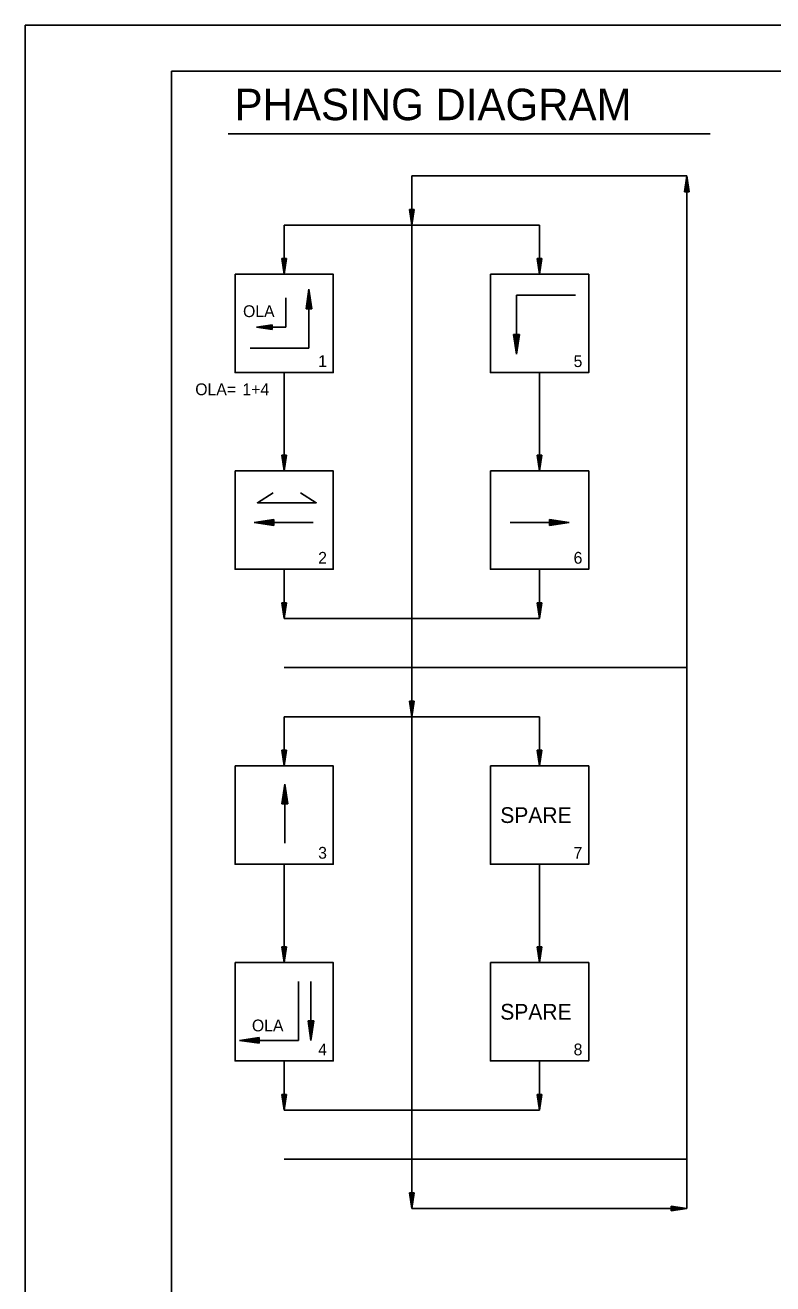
# Model space of a CAD drawing. Extents: x 1710114 to 1711114, y 557211 to 557851.
# Drawn here: x 1710114.3 to 1710304.6, y 557531.1 to 557851.1 of the extents above; entities that cross this region are included whole.
import ezdxf

# ---------------------------------------------------------------- set-up
doc = ezdxf.new("R2010")
doc.units = 0
for name, color, linetype in [('E_Existing ROW', 7, 'Continuous'), ('R_Alt Surface', 7, 'Continuous'), ('R_Alt Surface Annot', 7, 'Continuous'), ('R_Detour', 7, 'Continuous'), ('R_Dimension', 7, 'Continuous')]:
    doc.layers.add(name, color=color, linetype=linetype)

msp = doc.modelspace()

# ---------------------------------------------------------------- linework, layer by layer
at = {"layer": 'E_Existing ROW'}
for p, q in [((1710212.73, 557550.31), (1710212.73, 557812.81)), ((1710212.73, 557812.81), (1710282.73, 557812.81)), ((1710282.73, 557812.81), (1710282.73, 557550.31)), ((1710180.23, 557787.81), (1710180.23, 557800.31)), ((1710180.23, 557800.31), (1710245.23, 557800.31)), ((1710245.23, 557787.81), (1710245.23, 557800.31)), ((1710185.8, 557779.07), (1710186.55, 557784.07)), ((1710186.55, 557769.07), (1710186.55, 557784.07)), ((1710186.55, 557784.07), (1710187.3, 557779.07)), ((1710180.67, 557781.85), (1710180.67, 557774.35)), ((1710186.55, 557783.24), (1710185.92, 557779.07)), ((1710186.05, 557779.07), (1710186.55, 557782.38)), ((1710186.55, 557781.54), (1710186.18, 557779.07)), ((1710187.17, 557779.07), (1710186.55, 557783.24)), ((1710186.55, 557782.38), (1710187.05, 557779.07)), ((1710186.92, 557779.07), (1710186.55, 557781.54)), ((1710254.34, 557782.53), (1710239.34, 557782.53)), ((1710239.34, 557782.53), (1710239.34, 557767.53)), ((1710185.8, 557779.07), (1710187.3, 557779.07)), ((1710186.31, 557779.07), (1710186.55, 557780.7)), ((1710186.55, 557779.86), (1710186.43, 557779.07)), ((1710186.55, 557780.7), (1710186.79, 557779.07)), ((1710186.67, 557779.07), (1710186.55, 557779.86)), ((1710177.17, 557774.95), (1710173.17, 557774.35)), ((1710173.84, 557774.35), (1710177.17, 557774.85)), ((1710177.17, 557774.75), (1710174.53, 557774.35)), ((1710175.2, 557774.35), (1710177.17, 557774.65)), ((1710177.17, 557774.54), (1710175.87, 557774.35)), ((1710176.54, 557774.35), (1710177.17, 557774.44)), ((1710177.17, 557774.95), (1710177.17, 557773.75)), ((1710180.67, 557774.35), (1710173.17, 557774.35)), ((1710173.17, 557774.35), (1710177.17, 557773.75)), ((1710177.17, 557773.85), (1710173.84, 557774.35)), ((1710174.53, 557774.35), (1710177.17, 557773.95)), ((1710177.17, 557774.05), (1710175.2, 557774.35)), ((1710175.87, 557774.35), (1710177.17, 557774.15)), ((1710177.17, 557774.25), (1710176.54, 557774.35)), ((1710239.34, 557767.53), (1710238.59, 557772.53)), ((1710240.09, 557772.53), (1710238.59, 557772.53)), ((1710238.71, 557772.53), (1710239.34, 557768.37)), ((1710239.34, 557769.23), (1710238.84, 557772.53)), ((1710238.96, 557772.53), (1710239.34, 557770.06)), ((1710239.34, 557770.91), (1710239.09, 557772.53)), ((1710239.22, 557772.53), (1710239.34, 557771.74)), ((1710239.34, 557771.74), (1710239.45, 557772.53)), ((1710239.58, 557772.53), (1710239.34, 557770.91)), ((1710239.34, 557770.06), (1710239.71, 557772.53)), ((1710239.83, 557772.53), (1710239.34, 557769.23)), ((1710239.34, 557768.37), (1710239.96, 557772.53)), ((1710240.09, 557772.53), (1710239.34, 557767.53)), ((1710171.55, 557769.07), (1710186.55, 557769.07)), ((1710180.23, 557737.81), (1710180.23, 557762.81)), ((1710245.23, 557737.81), (1710245.23, 557762.81)), ((1710172.6, 557724.72), (1710177.6, 557725.47)), ((1710187.6, 557724.72), (1710172.6, 557724.72)), ((1710177.6, 557723.97), (1710172.6, 557724.72)), ((1710177.6, 557725.34), (1710173.43, 557724.72)), ((1710173.43, 557724.72), (1710177.6, 557724.09)), ((1710174.29, 557724.72), (1710177.6, 557725.21)), ((1710177.6, 557724.22), (1710174.29, 557724.72)), ((1710177.6, 557725.09), (1710175.13, 557724.72)), ((1710175.13, 557724.72), (1710177.6, 557724.34)), ((1710175.97, 557724.72), (1710177.6, 557724.96)), ((1710177.6, 557724.47), (1710175.97, 557724.72)), ((1710177.6, 557724.83), (1710176.81, 557724.72)), ((1710176.81, 557724.72), (1710177.6, 557724.6)), ((1710177.6, 557723.97), (1710177.6, 557725.47)), ((1710237.76, 557724.72), (1710252.76, 557724.72)), ((1710247.76, 557725.47), (1710252.76, 557724.72)), ((1710247.76, 557725.47), (1710247.76, 557723.97)), ((1710251.92, 557724.72), (1710247.76, 557725.34)), ((1710247.76, 557725.21), (1710251.06, 557724.72)), ((1710250.23, 557724.72), (1710247.76, 557725.09)), ((1710247.76, 557724.96), (1710249.38, 557724.72)), ((1710248.55, 557724.72), (1710247.76, 557724.83)), ((1710252.76, 557724.72), (1710247.76, 557723.97)), ((1710247.76, 557724.09), (1710251.92, 557724.72)), ((1710251.06, 557724.72), (1710247.76, 557724.22)), ((1710247.76, 557724.34), (1710250.23, 557724.72)), ((1710249.38, 557724.72), (1710247.76, 557724.47)), ((1710247.76, 557724.6), (1710248.55, 557724.72)), ((1710180.23, 557700.31), (1710180.23, 557712.81)), ((1710245.23, 557700.31), (1710245.23, 557712.81)), ((1710180.23, 557700.31), (1710245.23, 557700.31)), ((1710180.23, 557687.81), (1710282.73, 557687.81)), ((1710180.23, 557675.31), (1710245.23, 557675.31)), ((1710180.23, 557662.81), (1710180.23, 557675.31)), ((1710245.23, 557662.81), (1710245.23, 557675.31)), ((1710179.66, 557653.15), (1710180.41, 557658.15)), ((1710180.41, 557657.32), (1710179.79, 557653.15)), ((1710179.92, 557653.15), (1710180.41, 557656.46)), ((1710180.41, 557643.15), (1710180.41, 557658.15)), ((1710180.41, 557658.15), (1710181.16, 557653.15)), ((1710181.04, 557653.15), (1710180.41, 557657.32)), ((1710180.41, 557656.46), (1710180.91, 557653.15)), ((1710179.66, 557653.15), (1710181.16, 557653.15)), ((1710180.41, 557655.63), (1710180.04, 557653.15)), ((1710180.17, 557653.15), (1710180.41, 557654.78)), ((1710180.41, 557653.94), (1710180.3, 557653.15)), ((1710180.79, 557653.15), (1710180.41, 557655.63)), ((1710180.41, 557654.78), (1710180.66, 557653.15)), ((1710180.53, 557653.15), (1710180.41, 557653.94)), ((1710180.23, 557612.81), (1710180.23, 557637.81)), ((1710245.23, 557612.81), (1710245.23, 557637.81)), ((1710183.86, 557608.04), (1710183.86, 557593.04)), ((1710187.06, 557608.04), (1710187.06, 557593.04)), ((1710187.06, 557593.04), (1710186.31, 557598.04)), ((1710187.81, 557598.04), (1710186.31, 557598.04)), ((1710186.43, 557598.04), (1710187.06, 557593.87)), ((1710187.06, 557594.73), (1710186.56, 557598.04)), ((1710186.69, 557598.04), (1710187.06, 557595.57)), ((1710187.06, 557596.41), (1710186.81, 557598.04)), ((1710186.94, 557598.04), (1710187.06, 557597.25)), ((1710187.06, 557597.25), (1710187.18, 557598.04)), ((1710187.3, 557598.04), (1710187.06, 557596.41)), ((1710187.06, 557595.57), (1710187.43, 557598.04)), ((1710187.56, 557598.04), (1710187.06, 557594.73)), ((1710187.06, 557593.87), (1710187.68, 557598.04)), ((1710187.81, 557598.04), (1710187.06, 557593.04)), ((1710173.86, 557593.79), (1710168.86, 557593.04)), ((1710183.86, 557593.04), (1710168.86, 557593.04)), ((1710168.86, 557593.04), (1710173.86, 557592.29)), ((1710169.69, 557593.04), (1710173.86, 557593.66)), ((1710173.86, 557592.41), (1710169.69, 557593.04)), ((1710173.86, 557593.54), (1710170.55, 557593.04)), ((1710170.55, 557593.04), (1710173.86, 557592.54)), ((1710171.38, 557593.04), (1710173.86, 557593.41)), ((1710173.86, 557592.67), (1710171.38, 557593.04)), ((1710173.86, 557593.28), (1710172.23, 557593.04)), ((1710172.23, 557593.04), (1710173.86, 557592.79)), ((1710173.07, 557593.04), (1710173.86, 557593.16)), ((1710173.86, 557592.92), (1710173.07, 557593.04)), ((1710173.86, 557593.79), (1710173.86, 557592.29)), ((1710180.23, 557575.31), (1710180.23, 557587.81)), ((1710245.23, 557575.31), (1710245.23, 557587.81)), ((1710180.23, 557575.31), (1710245.23, 557575.31)), ((1710180.23, 557562.81), (1710282.73, 557562.81)), ((1710212.73, 557550.31), (1710282.73, 557550.31))]:
    msp.add_line(p, q, dxfattribs=at)
for points in [[(1710167.73, 557787.81), (1710192.73, 557787.81), (1710192.73, 557762.81), (1710167.73, 557762.81)], [(1710232.73, 557787.81), (1710257.73, 557787.81), (1710257.73, 557762.81), (1710232.73, 557762.81)], [(1710167.73, 557737.81), (1710192.73, 557737.81), (1710192.73, 557712.81), (1710167.73, 557712.81)], [(1710232.73, 557737.81), (1710257.73, 557737.81), (1710257.73, 557712.81), (1710232.73, 557712.81)], [(1710167.73, 557662.81), (1710192.73, 557662.81), (1710192.73, 557637.81), (1710167.73, 557637.81)], [(1710232.73, 557662.81), (1710257.73, 557662.81), (1710257.73, 557637.81), (1710232.73, 557637.81)], [(1710167.73, 557612.81), (1710192.73, 557612.81), (1710192.73, 557587.81), (1710167.73, 557587.81)], [(1710232.73, 557612.81), (1710257.73, 557612.81), (1710257.73, 557587.81), (1710232.73, 557587.81)]]:
    msp.add_lwpolyline(points, close=True, dxfattribs=at)
msp.add_lwpolyline([(1710177.41, 557732.22), (1710173.41, 557729.72), (1710188.41, 557729.72), (1710184.41, 557732.22)], dxfattribs=at)
at = {"layer": 'R_Alt Surface'}
for p, q in [((1710151.54, 557839.47), (1711100.08, 557839.47)), ((1710151.54, 557223.09), (1710151.54, 557839.47))]:
    msp.add_line(p, q, dxfattribs=at)
at = {"layer": 'R_Alt Surface Annot'}
msp.add_line((1710114.34, 557851.15), (1711114.34, 557851.15), dxfattribs=at)
msp.add_lwpolyline([(1710114.32, 557851.15), (1711114.34, 557851.15), (1711114.34, 557211.14), (1710114.32, 557211.14)], close=True, dxfattribs=at)
at = {"layer": 'R_Detour'}
for p, q in [((1710282.13, 557808.81), (1710282.73, 557812.81)), ((1710283.33, 557808.81), (1710282.73, 557812.81)), ((1710282.23, 557808.81), (1710282.73, 557812.14)), ((1710282.34, 557808.81), (1710282.73, 557811.45)), ((1710282.44, 557808.81), (1710282.73, 557810.79)), ((1710282.54, 557808.81), (1710282.73, 557810.11)), ((1710283.23, 557808.81), (1710282.73, 557812.14)), ((1710283.13, 557808.81), (1710282.73, 557811.45)), ((1710283.03, 557808.81), (1710282.73, 557810.79)), ((1710282.93, 557808.81), (1710282.73, 557810.11)), ((1710282.13, 557808.81), (1710283.33, 557808.81)), ((1710282.64, 557808.81), (1710282.73, 557809.44)), ((1710282.83, 557808.81), (1710282.73, 557809.44)), ((1710212.13, 557804.31), (1710212.73, 557800.31)), ((1710213.33, 557804.31), (1710212.13, 557804.31)), ((1710212.23, 557804.31), (1710212.73, 557800.98)), ((1710212.34, 557804.31), (1710212.73, 557801.67)), ((1710212.44, 557804.31), (1710212.73, 557802.33)), ((1710212.54, 557804.31), (1710212.73, 557803.01)), ((1710212.64, 557804.31), (1710212.73, 557803.68)), ((1710213.33, 557804.31), (1710212.73, 557800.31)), ((1710212.93, 557804.31), (1710212.73, 557803.01)), ((1710213.13, 557804.31), (1710212.73, 557801.67)), ((1710213.23, 557804.31), (1710212.73, 557800.98)), ((1710213.03, 557804.31), (1710212.73, 557802.33)), ((1710212.83, 557804.31), (1710212.73, 557803.68)), ((1710179.63, 557791.81), (1710180.23, 557787.81)), ((1710180.83, 557791.81), (1710179.63, 557791.81)), ((1710179.73, 557791.81), (1710180.23, 557788.48)), ((1710179.84, 557791.81), (1710180.23, 557789.17)), ((1710179.94, 557791.81), (1710180.23, 557789.83)), ((1710180.04, 557791.81), (1710180.23, 557790.51)), ((1710180.14, 557791.81), (1710180.23, 557791.18)), ((1710180.83, 557791.81), (1710180.23, 557787.81)), ((1710180.43, 557791.81), (1710180.23, 557790.51)), ((1710180.63, 557791.81), (1710180.23, 557789.17)), ((1710180.73, 557791.81), (1710180.23, 557788.48)), ((1710180.53, 557791.81), (1710180.23, 557789.83)), ((1710180.33, 557791.81), (1710180.23, 557791.18)), ((1710244.63, 557791.81), (1710245.23, 557787.81)), ((1710245.83, 557791.81), (1710244.63, 557791.81)), ((1710244.73, 557791.81), (1710245.23, 557788.48)), ((1710244.84, 557791.81), (1710245.23, 557789.17)), ((1710244.94, 557791.81), (1710245.23, 557789.83)), ((1710245.04, 557791.81), (1710245.23, 557790.51)), ((1710245.14, 557791.81), (1710245.23, 557791.18)), ((1710245.83, 557791.81), (1710245.23, 557787.81)), ((1710245.43, 557791.81), (1710245.23, 557790.51)), ((1710245.63, 557791.81), (1710245.23, 557789.17)), ((1710245.73, 557791.81), (1710245.23, 557788.48)), ((1710245.53, 557791.81), (1710245.23, 557789.83)), ((1710245.33, 557791.81), (1710245.23, 557791.18)), ((1710179.63, 557741.81), (1710180.23, 557737.81)), ((1710180.83, 557741.81), (1710179.63, 557741.81)), ((1710179.73, 557741.81), (1710180.23, 557738.48)), ((1710179.84, 557741.81), (1710180.23, 557739.17)), ((1710179.94, 557741.81), (1710180.23, 557739.83)), ((1710180.04, 557741.81), (1710180.23, 557740.51)), ((1710180.14, 557741.81), (1710180.23, 557741.18)), ((1710180.83, 557741.81), (1710180.23, 557737.81)), ((1710180.43, 557741.81), (1710180.23, 557740.51)), ((1710180.63, 557741.81), (1710180.23, 557739.17)), ((1710180.73, 557741.81), (1710180.23, 557738.48)), ((1710180.53, 557741.81), (1710180.23, 557739.83)), ((1710180.33, 557741.81), (1710180.23, 557741.18)), ((1710244.63, 557741.81), (1710245.23, 557737.81)), ((1710245.83, 557741.81), (1710244.63, 557741.81)), ((1710244.73, 557741.81), (1710245.23, 557738.48)), ((1710244.84, 557741.81), (1710245.23, 557739.17)), ((1710244.94, 557741.81), (1710245.23, 557739.83)), ((1710245.04, 557741.81), (1710245.23, 557740.51)), ((1710245.14, 557741.81), (1710245.23, 557741.18)), ((1710245.83, 557741.81), (1710245.23, 557737.81)), ((1710245.43, 557741.81), (1710245.23, 557740.51)), ((1710245.63, 557741.81), (1710245.23, 557739.17)), ((1710245.73, 557741.81), (1710245.23, 557738.48)), ((1710245.53, 557741.81), (1710245.23, 557739.83)), ((1710245.33, 557741.81), (1710245.23, 557741.18)), ((1710179.63, 557704.31), (1710180.23, 557700.31)), ((1710180.83, 557704.31), (1710179.63, 557704.31)), ((1710179.73, 557704.31), (1710180.23, 557700.98)), ((1710179.84, 557704.31), (1710180.23, 557701.67)), ((1710179.94, 557704.31), (1710180.23, 557702.33)), ((1710180.04, 557704.31), (1710180.23, 557703.01)), ((1710180.14, 557704.31), (1710180.23, 557703.68)), ((1710180.83, 557704.31), (1710180.23, 557700.31)), ((1710180.43, 557704.31), (1710180.23, 557703.01)), ((1710180.63, 557704.31), (1710180.23, 557701.67)), ((1710180.73, 557704.31), (1710180.23, 557700.98)), ((1710180.53, 557704.31), (1710180.23, 557702.33)), ((1710180.33, 557704.31), (1710180.23, 557703.68)), ((1710244.63, 557704.31), (1710245.23, 557700.31)), ((1710245.83, 557704.31), (1710244.63, 557704.31)), ((1710244.73, 557704.31), (1710245.23, 557700.98)), ((1710244.84, 557704.31), (1710245.23, 557701.67)), ((1710244.94, 557704.31), (1710245.23, 557702.33)), ((1710245.04, 557704.31), (1710245.23, 557703.01)), ((1710245.14, 557704.31), (1710245.23, 557703.68)), ((1710245.83, 557704.31), (1710245.23, 557700.31)), ((1710245.43, 557704.31), (1710245.23, 557703.01)), ((1710245.63, 557704.31), (1710245.23, 557701.67)), ((1710245.73, 557704.31), (1710245.23, 557700.98)), ((1710245.53, 557704.31), (1710245.23, 557702.33)), ((1710245.33, 557704.31), (1710245.23, 557703.68)), ((1710212.13, 557679.31), (1710212.73, 557675.31)), ((1710213.33, 557679.31), (1710212.13, 557679.31)), ((1710212.23, 557679.31), (1710212.73, 557675.98)), ((1710212.34, 557679.31), (1710212.73, 557676.67)), ((1710212.44, 557679.31), (1710212.73, 557677.33)), ((1710212.54, 557679.31), (1710212.73, 557678.01)), ((1710212.64, 557679.31), (1710212.73, 557678.68)), ((1710213.33, 557679.31), (1710212.73, 557675.31)), ((1710212.93, 557679.31), (1710212.73, 557678.01)), ((1710213.13, 557679.31), (1710212.73, 557676.67)), ((1710213.23, 557679.31), (1710212.73, 557675.98)), ((1710213.03, 557679.31), (1710212.73, 557677.33)), ((1710212.83, 557679.31), (1710212.73, 557678.68)), ((1710179.63, 557666.81), (1710180.23, 557662.81)), ((1710180.83, 557666.81), (1710179.63, 557666.81)), ((1710179.73, 557666.81), (1710180.23, 557663.48)), ((1710179.84, 557666.81), (1710180.23, 557664.17)), ((1710179.94, 557666.81), (1710180.23, 557664.83)), ((1710180.04, 557666.81), (1710180.23, 557665.51)), ((1710180.14, 557666.81), (1710180.23, 557666.18)), ((1710180.83, 557666.81), (1710180.23, 557662.81)), ((1710180.43, 557666.81), (1710180.23, 557665.51)), ((1710180.63, 557666.81), (1710180.23, 557664.17)), ((1710180.73, 557666.81), (1710180.23, 557663.48)), ((1710180.53, 557666.81), (1710180.23, 557664.83)), ((1710180.33, 557666.81), (1710180.23, 557666.18)), ((1710244.63, 557666.81), (1710245.23, 557662.81)), ((1710245.83, 557666.81), (1710244.63, 557666.81)), ((1710244.73, 557666.81), (1710245.23, 557663.48)), ((1710244.84, 557666.81), (1710245.23, 557664.17)), ((1710244.94, 557666.81), (1710245.23, 557664.83)), ((1710245.04, 557666.81), (1710245.23, 557665.51)), ((1710245.14, 557666.81), (1710245.23, 557666.18)), ((1710245.83, 557666.81), (1710245.23, 557662.81)), ((1710245.43, 557666.81), (1710245.23, 557665.51)), ((1710245.63, 557666.81), (1710245.23, 557664.17)), ((1710245.73, 557666.81), (1710245.23, 557663.48)), ((1710245.53, 557666.81), (1710245.23, 557664.83)), ((1710245.33, 557666.81), (1710245.23, 557666.18)), ((1710179.63, 557616.81), (1710180.23, 557612.81)), ((1710180.83, 557616.81), (1710179.63, 557616.81)), ((1710179.73, 557616.81), (1710180.23, 557613.48)), ((1710179.84, 557616.81), (1710180.23, 557614.17)), ((1710179.94, 557616.81), (1710180.23, 557614.83)), ((1710180.04, 557616.81), (1710180.23, 557615.51)), ((1710180.14, 557616.81), (1710180.23, 557616.18)), ((1710180.83, 557616.81), (1710180.23, 557612.81)), ((1710180.43, 557616.81), (1710180.23, 557615.51)), ((1710180.63, 557616.81), (1710180.23, 557614.17)), ((1710180.73, 557616.81), (1710180.23, 557613.48)), ((1710180.53, 557616.81), (1710180.23, 557614.83)), ((1710180.33, 557616.81), (1710180.23, 557616.18)), ((1710244.63, 557616.81), (1710245.23, 557612.81)), ((1710245.83, 557616.81), (1710244.63, 557616.81)), ((1710244.73, 557616.81), (1710245.23, 557613.48)), ((1710244.84, 557616.81), (1710245.23, 557614.17)), ((1710244.94, 557616.81), (1710245.23, 557614.83)), ((1710245.04, 557616.81), (1710245.23, 557615.51)), ((1710245.14, 557616.81), (1710245.23, 557616.18)), ((1710245.83, 557616.81), (1710245.23, 557612.81)), ((1710245.43, 557616.81), (1710245.23, 557615.51)), ((1710245.63, 557616.81), (1710245.23, 557614.17)), ((1710245.73, 557616.81), (1710245.23, 557613.48)), ((1710245.53, 557616.81), (1710245.23, 557614.83)), ((1710245.33, 557616.81), (1710245.23, 557616.18)), ((1710179.63, 557579.31), (1710180.23, 557575.31)), ((1710180.83, 557579.31), (1710179.63, 557579.31)), ((1710179.73, 557579.31), (1710180.23, 557575.98)), ((1710179.84, 557579.31), (1710180.23, 557576.67)), ((1710179.94, 557579.31), (1710180.23, 557577.33)), ((1710180.04, 557579.31), (1710180.23, 557578.01)), ((1710180.14, 557579.31), (1710180.23, 557578.68)), ((1710180.83, 557579.31), (1710180.23, 557575.31)), ((1710180.43, 557579.31), (1710180.23, 557578.01)), ((1710180.63, 557579.31), (1710180.23, 557576.67)), ((1710180.73, 557579.31), (1710180.23, 557575.98)), ((1710180.53, 557579.31), (1710180.23, 557577.33)), ((1710180.33, 557579.31), (1710180.23, 557578.68)), ((1710244.63, 557579.31), (1710245.23, 557575.31)), ((1710245.83, 557579.31), (1710244.63, 557579.31)), ((1710244.73, 557579.31), (1710245.23, 557575.98)), ((1710244.84, 557579.31), (1710245.23, 557576.67)), ((1710244.94, 557579.31), (1710245.23, 557577.33)), ((1710245.04, 557579.31), (1710245.23, 557578.01)), ((1710245.14, 557579.31), (1710245.23, 557578.68)), ((1710245.83, 557579.31), (1710245.23, 557575.31)), ((1710245.43, 557579.31), (1710245.23, 557578.01)), ((1710245.63, 557579.31), (1710245.23, 557576.67)), ((1710245.73, 557579.31), (1710245.23, 557575.98)), ((1710245.53, 557579.31), (1710245.23, 557577.33)), ((1710245.33, 557579.31), (1710245.23, 557578.68)), ((1710212.13, 557554.31), (1710212.73, 557550.31)), ((1710213.33, 557554.31), (1710212.13, 557554.31)), ((1710212.23, 557554.31), (1710212.73, 557550.98)), ((1710212.34, 557554.31), (1710212.73, 557551.67)), ((1710212.44, 557554.31), (1710212.73, 557552.33)), ((1710212.54, 557554.31), (1710212.73, 557553.01)), ((1710212.64, 557554.31), (1710212.73, 557553.68)), ((1710213.33, 557554.31), (1710212.73, 557550.31)), ((1710212.93, 557554.31), (1710212.73, 557553.01)), ((1710213.13, 557554.31), (1710212.73, 557551.67)), ((1710213.23, 557554.31), (1710212.73, 557550.98)), ((1710213.03, 557554.31), (1710212.73, 557552.33)), ((1710212.83, 557554.31), (1710212.73, 557553.68)), ((1710278.73, 557550.91), (1710282.73, 557550.31)), ((1710278.73, 557550.91), (1710278.73, 557549.71)), ((1710278.73, 557550.81), (1710282.07, 557550.31)), ((1710278.73, 557550.71), (1710281.38, 557550.31)), ((1710278.73, 557550.61), (1710280.71, 557550.31)), ((1710278.73, 557550.5), (1710280.03, 557550.31)), ((1710278.73, 557550.4), (1710279.37, 557550.31)), ((1710278.73, 557549.71), (1710282.73, 557550.31)), ((1710278.73, 557550.11), (1710280.03, 557550.31)), ((1710278.73, 557549.91), (1710281.38, 557550.31)), ((1710278.73, 557549.81), (1710282.07, 557550.31)), ((1710278.73, 557550.01), (1710280.71, 557550.31)), ((1710278.73, 557550.22), (1710279.37, 557550.31))]:
    msp.add_line(p, q, dxfattribs=at)
at = {"layer": 'R_Dimension'}
msp.add_line((1710166.01, 557823.52), (1710288.65, 557823.52), dxfattribs=at)

# ---------------------------------------------------------------- texts
at = {"layer": 'E_Existing ROW'}
for s, height, p in [('OLA', 3, (1710169.77, 557776.93)), ('OLA=', 3, (1710157.61, 557757.07)), ('1+4', 3, (1710169.61, 557757.07)), ('SPARE', 4, (1710235.23, 557648.31)), ('SPARE', 4, (1710235.23, 557598.31)), ('OLA', 3, (1710172.03, 557595.33))]:
    msp.add_text(s, height=height, dxfattribs=at).set_placement(p)
at = {"layer": 'R_Dimension'}
for s, height, p in [('PHASING DIAGRAM', 8, (1710167.6, 557826.99)), ('1', 3, (1710188.89, 557764.23)), ('5', 3, (1710253.89, 557764.23)), ('2', 3, (1710188.89, 557714.23)), ('6', 3, (1710253.89, 557714.23)), ('3', 3, (1710188.89, 557639.23)), ('7', 3, (1710253.89, 557639.23)), ('4', 3, (1710188.89, 557589.23)), ('8', 3, (1710253.89, 557589.23))]:
    msp.add_text(s, height=height, dxfattribs=at).set_placement(p)

doc.saveas('drawing.dxf')
